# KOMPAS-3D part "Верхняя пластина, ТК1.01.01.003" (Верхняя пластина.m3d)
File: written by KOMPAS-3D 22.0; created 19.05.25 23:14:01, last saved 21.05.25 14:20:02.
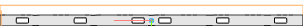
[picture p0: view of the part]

Document properties: Автор: user; Полное имя файла: КД\Верхняя пластина.cdw

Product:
- Part/product: Верхняя пластина  | designation ТК1.01.01.003
    Масса: 41.469866
    Форматы листов документа: A4@4~3

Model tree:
1. Эскиз:1
2. Элемент выдавливания:1
     Расстояние 1 = 8
3. Линейный размер:1  (with: Элемент выдавливания:1)
     Значение = 168
4. Линейный размер:2  (with: Элемент выдавливания:1)
     Значение = 4470
5. Эскиз:2  (with: Элемент выдавливания:1)
6. Элемент выдавливания:2
     Расстояние 2 = 8
7. Скругление:1  (with: Элемент выдавливания:2)
     Радиус = 10
8. Массив по сетке:1  (with: Элемент выдавливания:2, Скругление:1, Элемент выдавливания:1)  (3 pattern instances)
     Шаг 1 = 854; Угол раствора = 90; Геометрический массив = 128
9. Зеркальный массив:1
10. Экземпляр ( 1 )
11. Экземпляр ( 2 )  (with: Массив по сетке:1, Экземпляр ( 1 ), Элемент выдавливания:2, Скругление:1)

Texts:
  ТК1.01.01.003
